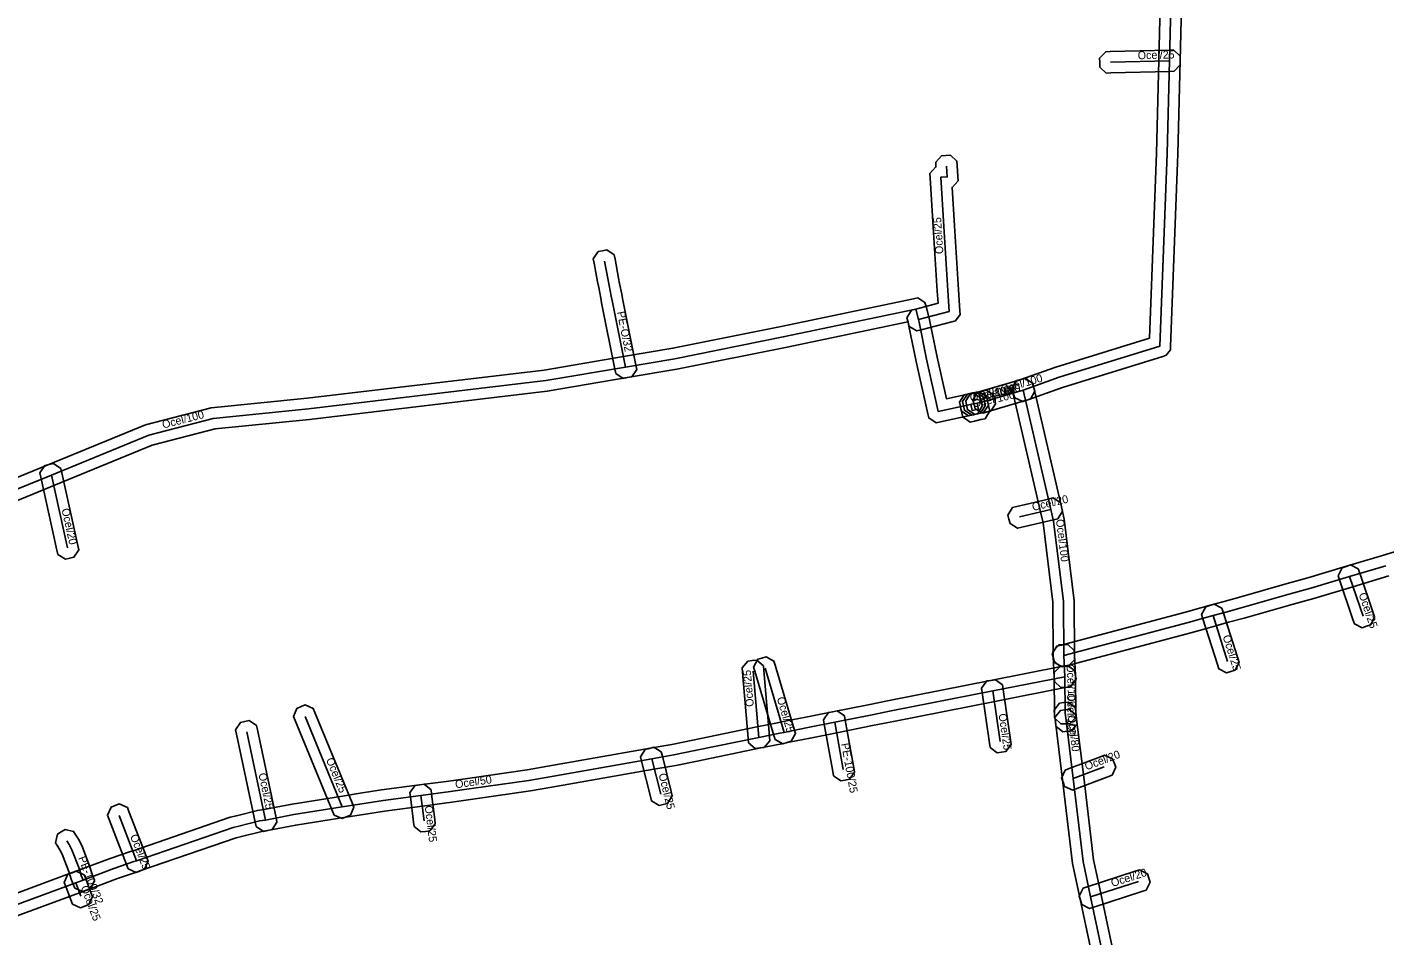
# Model space of a CAD drawing. Extents: x -569373 to -565022, y -1135090 to -1131496.
# Drawn here: x -565551.4 to -565424.2, y -1133791.5 to -1133706.4 of the extents above; entities that cross this region are included whole.
import ezdxf

# ---------------------------------------------------------------- set-up
doc = ezdxf.new("R2010")
doc.units = 0
for name, color, linetype in [('1', 7, 'Continuous'), ('24', 7, 'Continuous'), ('30', 7, 'Continuous')]:
    doc.layers.add(name, color=color, linetype=linetype)

msp = doc.modelspace()

# ---------------------------------------------------------------- linework, layer by layer
at = {"layer": '1'}
for points in [[(-565443.139, -1133700.516), (-565443.35, -1133709.573), (-565443.55, -1133718.271), (-565444.251, -1133736.319), (-565444.263, -1133736.637), (-565444.651, -1133737.142), (-565444.955, -1133737.236), (-565454.374, -1133740.139), (-565457.703, -1133741.331), (-565458.093, -1133741.471), (-565458.841, -1133741.117), (-565458.981, -1133740.727), (-565459.121, -1133740.337), (-565458.767, -1133739.589), (-565458.377, -1133739.449), (-565455.006, -1133738.241), (-565446.222, -1133735.533), (-565445.55, -1133718.209), (-565445.35, -1133709.527), (-565445.141, -1133700.544)], [(-565553.833, -1133749.207), (-565549.479, -1133747.425), (-565540.286, -1133743.659), (-565534.116, -1133742.063), (-565525.119, -1133741.166), (-565502.923, -1133738.52), (-565495.492, -1133737.26), (-565490.872, -1133736.477), (-565480.731, -1133734.44), (-565468.325, -1133731.841), (-565467.933, -1133731.759), (-565467.253, -1133732.181), (-565467.152, -1133732.568), (-565466.9, -1133733.537), (-565466.834, -1133733.813), (-565466.122, -1133737.301), (-565465.251, -1133741.203), (-565463.227, -1133740.766), (-565463.203, -1133740.76), (-565462.801, -1133740.659), (-565462.09, -1133741.085), (-565461.99, -1133741.487), (-565461.889, -1133741.889), (-565462.315, -1133742.6), (-565462.717, -1133742.7), (-565462.773, -1133742.714), (-565465.799, -1133743.367), (-565466.202, -1133743.454), (-565466.896, -1133743.01), (-565466.986, -1133742.608), (-565468.078, -1133737.719), (-565468.786, -1133734.247), (-565468.84, -1133734.023), (-565468.848, -1133733.994), (-565480.329, -1133736.4), (-565490.508, -1133738.443), (-565495.158, -1133739.232), (-565502.637, -1133740.5), (-565524.901, -1133743.154), (-565533.764, -1133744.037), (-565539.654, -1133745.561), (-565548.721, -1133749.275), (-565552.967, -1133751.013)], [(-565423.803, -1133757.8), (-565427.184, -1133758.808), (-565430.831, -1133759.9), (-565432.767, -1133760.447), (-565437.351, -1133761.743), (-565438.803, -1133762.144), (-565439.995, -1133762.474), (-565440.885, -1133762.718), (-565442.34, -1133763.116), (-565453.994, -1133766.207), (-565454.394, -1133766.313), (-565455.111, -1133765.897), (-565455.217, -1133765.496), (-565455.323, -1133765.096), (-565454.907, -1133764.379), (-565454.506, -1133764.273), (-565442.86, -1133761.184), (-565441.413, -1133760.788), (-565440.525, -1133760.546), (-565439.337, -1133760.216), (-565437.889, -1133759.817), (-565433.311, -1133758.523), (-565431.389, -1133757.98), (-565427.756, -1133756.892), (-565424.375, -1133755.884), (-565422.452, -1133755.31)], [(-565553.339, -1133787.878), (-565547.156, -1133785.592), (-565546.477, -1133785.342), (-565543.587, -1133784.268), (-565541.681, -1133783.613), (-565541.441, -1133783.533), (-565532.353, -1133780.4), (-565531.77, -1133780.256), (-565529.789, -1133779.769), (-565529.204, -1133779.675), (-565526.542, -1133779.165), (-565523.985, -1133778.762), (-565522.006, -1133778.452), (-565520.159, -1133778.158), (-565518.174, -1133777.84), (-565514.6, -1133777.369), (-565511.856, -1133777.009), (-565509.881, -1133776.727), (-565504.527, -1133775.962), (-565502.572, -1133775.618), (-565493.003, -1133773.935), (-565490.957, -1133773.578), (-565489.013, -1133773.177), (-565483.019, -1133771.94), (-565481.056, -1133771.549), (-565480.656, -1133771.469), (-565480.375, -1133771.413), (-565478.416, -1133771.019), (-565475.905, -1133770.519), (-565472.565, -1133769.859), (-565470.605, -1133769.469), (-565461.104, -1133767.589), (-565454.343, -1133766.259), (-565453.937, -1133766.179), (-565453.249, -1133766.641), (-565453.169, -1133767.047), (-565453.089, -1133767.453), (-565453.551, -1133768.141), (-565453.957, -1133768.221), (-565460.716, -1133769.551), (-565470.215, -1133771.431), (-565472.175, -1133771.821), (-565475.515, -1133772.481), (-565478.024, -1133772.981), (-565479.983, -1133773.375), (-565480.264, -1133773.431), (-565480.664, -1133773.511), (-565482.621, -1133773.9), (-565488.609, -1133775.135), (-565490.583, -1133775.542), (-565492.657, -1133775.905), (-565502.226, -1133777.588), (-565504.213, -1133777.938), (-565509.599, -1133778.707), (-565511.584, -1133778.991), (-565514.34, -1133779.351), (-565517.886, -1133779.82), (-565519.843, -1133780.132), (-565521.694, -1133780.428), (-565523.675, -1133780.738), (-565526.198, -1133781.135), (-565528.856, -1133781.645), (-565529.391, -1133781.731), (-565531.292, -1133782.198), (-565531.787, -1133782.32), (-565540.799, -1133785.427), (-565541.039, -1133785.507), (-565542.913, -1133786.152), (-565545.783, -1133787.218), (-565546.464, -1133787.468), (-565552.645, -1133789.754)], [(-565448.326, -1133808.76), (-565452.718, -1133788.077), (-565453.428, -1133784.724), (-565454.373, -1133776.89), (-565455.033, -1133771.471), (-565455.083, -1133771.06), (-565454.572, -1133770.407), (-565454.161, -1133770.357), (-565453.75, -1133770.307), (-565453.097, -1133770.818), (-565453.047, -1133771.229), (-565452.387, -1133776.65), (-565451.452, -1133784.396), (-565450.762, -1133787.663), (-565446.374, -1133808.32)]]:
    msp.add_lwpolyline(points, dxfattribs=at)
for points in [[(-565443.909, -1133710.539), (-565444.323, -1133710.55), (-565449.853, -1133710.7), (-565450.267, -1133710.711), (-565450.869, -1133710.141), (-565450.88, -1133709.727), (-565450.891, -1133709.313), (-565450.321, -1133708.711), (-565449.907, -1133708.7), (-565444.377, -1133708.55), (-565443.963, -1133708.539), (-565443.361, -1133709.109), (-565443.35, -1133709.523), (-565443.339, -1133709.937)], [(-565466.237, -1133719.492), (-565466.227, -1133719.492), (-565466.228, -1133719.479), (-565466.252, -1133719.065), (-565465.702, -1133718.446), (-565465.289, -1133718.422), (-565464.875, -1133718.398), (-565464.256, -1133718.948), (-565464.232, -1133719.361), (-565464.172, -1133720.381), (-565464.147, -1133720.797), (-565464.426, -1133721.108), (-565464.704, -1133721.418), (-565464.708, -1133721.418), (-565464.482, -1133725.017), (-565464.102, -1133731.008), (-565463.982, -1133732.969), (-565463.96, -1133733.327), (-565464.382, -1133733.908), (-565464.729, -1133733.998), (-565467.619, -1133734.748), (-565468.02, -1133734.852), (-565468.734, -1133734.432), (-565468.838, -1133734.031), (-565468.942, -1133733.63), (-565468.522, -1133732.916), (-565468.121, -1133732.812), (-565466.028, -1133732.269), (-565466.098, -1133731.132), (-565466.478, -1133725.143), (-565466.768, -1133720.533), (-565466.794, -1133720.116), (-565466.516, -1133719.804)], [(-565496.225, -1133738.848), (-565496.306, -1133738.442), (-565497.547, -1133732.217), (-565497.632, -1133731.791), (-565497.824, -1133730.776), (-565497.92, -1133730.274), (-565498.253, -1133728.516), (-565498.33, -1133728.109), (-565497.863, -1133727.424), (-565497.456, -1133727.347), (-565497.049, -1133727.27), (-565496.364, -1133727.737), (-565496.287, -1133728.144), (-565495.954, -1133729.902), (-565495.86, -1133730.404), (-565495.668, -1133731.409), (-565495.585, -1133731.825), (-565494.344, -1133738.05), (-565494.263, -1133738.456), (-565494.723, -1133739.146), (-565495.129, -1133739.227), (-565495.535, -1133739.308)], [(-565462.38, -1133740.628), (-565461.983, -1133740.511), (-565458.323, -1133739.431), (-565457.926, -1133739.314), (-565457.198, -1133739.71), (-565457.081, -1133740.107), (-565456.964, -1133740.504), (-565457.36, -1133741.232), (-565457.757, -1133741.349), (-565461.417, -1133742.429), (-565461.814, -1133742.546), (-565462.542, -1133742.15), (-565462.659, -1133741.753), (-565462.776, -1133741.356)], [(-565457.159, -1133739.761), (-565457.066, -1133740.164), (-565454.476, -1133751.345), (-565454.214, -1133752.486), (-565453.27, -1133760.127), (-565453.25, -1133765.236), (-565453.248, -1133765.65), (-565453.832, -1133766.238), (-565454.246, -1133766.24), (-565454.66, -1133766.242), (-565455.248, -1133765.658), (-565455.25, -1133765.244), (-565455.27, -1133760.253), (-565456.186, -1133752.834), (-565456.424, -1133751.795), (-565459.014, -1133740.616), (-565459.108, -1133740.212), (-565458.669, -1133739.509), (-565458.266, -1133739.416), (-565457.862, -1133739.322)], [(-565462.771, -1133740.664), (-565462.762, -1133740.669), (-565462.586, -1133740.632), (-565462.181, -1133740.546), (-565461.486, -1133740.997), (-565461.4, -1133741.402), (-565461.334, -1133741.714), (-565461.276, -1133741.965), (-565461.182, -1133742.371), (-565461.404, -1133742.723), (-565461.625, -1133743.075), (-565462.031, -1133743.166), (-565462.611, -1133743.296), (-565463.017, -1133743.387), (-565463.367, -1133743.164), (-565463.717, -1133742.941), (-565463.807, -1133742.535), (-565463.937, -1133741.945), (-565464.026, -1133741.541), (-565463.58, -1133740.842), (-565463.175, -1133740.753)], [(-565463.568, -1133740.835), (-565463.162, -1133740.751), (-565462.871, -1133740.691), (-565462.465, -1133740.607), (-565461.774, -1133741.062), (-565461.69, -1133741.468), (-565461.606, -1133741.874), (-565462.061, -1133742.565), (-565462.467, -1133742.649), (-565462.758, -1133742.709), (-565463.164, -1133742.793), (-565463.855, -1133742.338), (-565463.939, -1133741.932), (-565464.023, -1133741.526)], [(-565463.277, -1133740.775), (-565462.871, -1133740.691), (-565462.58, -1133740.631), (-565462.174, -1133740.547), (-565461.483, -1133741.002), (-565461.399, -1133741.408), (-565461.315, -1133741.814), (-565461.77, -1133742.505), (-565462.176, -1133742.589), (-565462.467, -1133742.649), (-565462.873, -1133742.733), (-565463.564, -1133742.278), (-565463.648, -1133741.872), (-565463.732, -1133741.466)], [(-565462.986, -1133740.715), (-565462.58, -1133740.631), (-565461.902, -1133740.491), (-565461.496, -1133740.407), (-565460.805, -1133740.862), (-565460.721, -1133741.268), (-565460.637, -1133741.674), (-565461.092, -1133742.365), (-565461.498, -1133742.449), (-565462.176, -1133742.589), (-565462.582, -1133742.673), (-565463.273, -1133742.218), (-565463.357, -1133741.812), (-565463.441, -1133741.406)], [(-565548.212, -1133747.73), (-565548.123, -1133748.135), (-565546.623, -1133754.945), (-565546.534, -1133755.349), (-565546.98, -1133756.048), (-565547.385, -1133756.137), (-565547.789, -1133756.226), (-565548.488, -1133755.78), (-565548.577, -1133755.375), (-565550.077, -1133748.565), (-565550.166, -1133748.161), (-565549.72, -1133747.462), (-565549.315, -1133747.373), (-565548.911, -1133747.284)], [(-565454.817, -1133752.448), (-565455.22, -1133752.543), (-565458.18, -1133753.243), (-565458.583, -1133753.338), (-565459.288, -1133752.903), (-565459.383, -1133752.5), (-565459.478, -1133752.097), (-565459.043, -1133751.392), (-565458.64, -1133751.297), (-565455.68, -1133750.597), (-565455.277, -1133750.502), (-565454.572, -1133750.937), (-565454.477, -1133751.34), (-565454.382, -1133751.743)], [(-565426.656, -1133757.137), (-565426.523, -1133757.529), (-565425.263, -1133761.249), (-565425.13, -1133761.641), (-565425.497, -1133762.384), (-565425.889, -1133762.517), (-565426.281, -1133762.65), (-565427.024, -1133762.283), (-565427.157, -1133761.891), (-565428.417, -1133758.171), (-565428.55, -1133757.779), (-565428.183, -1133757.036), (-565427.791, -1133756.903), (-565427.399, -1133756.77)], [(-565439.432, -1133760.813), (-565439.307, -1133761.208), (-565437.947, -1133765.508), (-565437.822, -1133765.903), (-565438.203, -1133766.638), (-565438.598, -1133766.763), (-565438.993, -1133766.888), (-565439.728, -1133766.507), (-565439.853, -1133766.112), (-565441.213, -1133761.812), (-565441.338, -1133761.417), (-565440.957, -1133760.682), (-565440.562, -1133760.557), (-565440.167, -1133760.432)], [(-565453.272, -1133764.776), (-565453.251, -1133765.19), (-565453.151, -1133767.19), (-565453.13, -1133767.604), (-565453.686, -1133768.218), (-565454.1, -1133768.239), (-565454.514, -1133768.26), (-565455.128, -1133767.704), (-565455.149, -1133767.29), (-565455.249, -1133765.29), (-565455.27, -1133764.876), (-565454.714, -1133764.262), (-565454.3, -1133764.241), (-565453.886, -1133764.22)], [(-565483.781, -1133773.418), (-565483.816, -1133773.005), (-565484.346, -1133766.815), (-565484.382, -1133766.402), (-565483.848, -1133765.769), (-565483.435, -1133765.734), (-565483.022, -1133765.698), (-565482.389, -1133766.232), (-565482.354, -1133766.645), (-565481.824, -1133772.835), (-565481.788, -1133773.248), (-565482.322, -1133773.881), (-565482.735, -1133773.916), (-565483.148, -1133773.952)], [(-565481.301, -1133773.131), (-565481.419, -1133772.734), (-565483.199, -1133766.734), (-565483.317, -1133766.337), (-565482.921, -1133765.609), (-565482.524, -1133765.491), (-565482.127, -1133765.373), (-565481.399, -1133765.769), (-565481.281, -1133766.166), (-565479.501, -1133772.166), (-565479.383, -1133772.563), (-565479.779, -1133773.291), (-565480.176, -1133773.409), (-565480.573, -1133773.527)], [(-565453.154, -1133766.817), (-565453.15, -1133767.231), (-565453.12, -1133770.651), (-565453.116, -1133771.065), (-565453.697, -1133771.656), (-565454.111, -1133771.66), (-565454.525, -1133771.664), (-565455.116, -1133771.083), (-565455.12, -1133770.669), (-565455.15, -1133767.249), (-565455.154, -1133766.835), (-565454.573, -1133766.244), (-565454.159, -1133766.24), (-565453.745, -1133766.236)], [(-565459.98, -1133768.016), (-565459.92, -1133768.426), (-565459.23, -1133773.166), (-565459.17, -1133773.576), (-565459.666, -1133774.24), (-565460.076, -1133774.3), (-565460.486, -1133774.36), (-565461.15, -1133773.864), (-565461.21, -1133773.454), (-565461.9, -1133768.714), (-565461.96, -1133768.304), (-565461.464, -1133767.64), (-565461.054, -1133767.58), (-565460.644, -1133767.52)], [(-565522.618, -1133780.203), (-565522.775, -1133779.82), (-565526.255, -1133771.35), (-565526.412, -1133770.967), (-565526.093, -1133770.202), (-565525.71, -1133770.045), (-565525.327, -1133769.888), (-565524.562, -1133770.207), (-565524.405, -1133770.59), (-565520.925, -1133779.06), (-565520.768, -1133779.443), (-565521.087, -1133780.208), (-565521.47, -1133780.365), (-565521.853, -1133780.522)], [(-565453.175, -1133770.133), (-565453.127, -1133770.545), (-565453.047, -1133771.235), (-565452.999, -1133771.646), (-565453.513, -1133772.295), (-565453.925, -1133772.343), (-565454.336, -1133772.391), (-565454.985, -1133771.877), (-565455.033, -1133771.465), (-565455.113, -1133770.775), (-565455.161, -1133770.364), (-565454.647, -1133769.715), (-565454.235, -1133769.667), (-565453.824, -1133769.619)], [(-565529.922, -1133781.273), (-565530.008, -1133780.868), (-565531.758, -1133772.618), (-565531.844, -1133772.212), (-565531.393, -1133771.518), (-565530.988, -1133771.432), (-565530.582, -1133771.346), (-565529.888, -1133771.797), (-565529.802, -1133772.202), (-565528.052, -1133780.452), (-565527.966, -1133780.858), (-565528.417, -1133781.552), (-565528.822, -1133781.638), (-565529.228, -1133781.724)], [(-565475.821, -1133776.525), (-565475.894, -1133776.117), (-565476.694, -1133771.677), (-565476.767, -1133771.269), (-565476.295, -1133770.589), (-565475.887, -1133770.516), (-565475.479, -1133770.443), (-565474.799, -1133770.915), (-565474.726, -1133771.323), (-565473.926, -1133775.763), (-565473.853, -1133776.171), (-565474.325, -1133776.851), (-565474.733, -1133776.924), (-565475.141, -1133776.997)], [(-565491.959, -1133774.278), (-565491.859, -1133774.68), (-565491.039, -1133777.99), (-565490.94, -1133778.392), (-565491.368, -1133779.101), (-565491.77, -1133779.201), (-565492.172, -1133779.3), (-565492.881, -1133778.872), (-565492.981, -1133778.47), (-565493.801, -1133775.16), (-565493.9, -1133774.758), (-565493.472, -1133774.049), (-565493.07, -1133773.949), (-565492.668, -1133773.85)], [(-565454.121, -1133775.981), (-565453.734, -1133775.835), (-565450.824, -1133774.735), (-565450.436, -1133774.588), (-565449.681, -1133774.929), (-565449.535, -1133775.316), (-565449.388, -1133775.704), (-565449.729, -1133776.459), (-565450.116, -1133776.605), (-565453.026, -1133777.705), (-565453.414, -1133777.852), (-565454.169, -1133777.511), (-565454.315, -1133777.124), (-565454.462, -1133776.736)], [(-565513.528, -1133777.828), (-565513.477, -1133778.239), (-565513.187, -1133780.609), (-565513.137, -1133781.02), (-565513.648, -1133781.672), (-565514.059, -1133781.723), (-565514.47, -1133781.773), (-565515.122, -1133781.262), (-565515.173, -1133780.851), (-565515.463, -1133778.481), (-565515.513, -1133778.07), (-565515.002, -1133777.418), (-565514.591, -1133777.367), (-565514.18, -1133777.317)], [(-565541.903, -1133785.227), (-565542.053, -1133784.841), (-565543.693, -1133780.601), (-565543.842, -1133780.215), (-565543.507, -1133779.457), (-565543.121, -1133779.307), (-565542.735, -1133779.158), (-565541.977, -1133779.493), (-565541.827, -1133779.879), (-565540.187, -1133784.119), (-565540.038, -1133784.505), (-565540.373, -1133785.263), (-565540.759, -1133785.413), (-565541.145, -1133785.562)], [(-565546.902, -1133787.039), (-565547.057, -1133786.655), (-565547.246, -1133786.187), (-565547.419, -1133785.589), (-565548.086, -1133783.865), (-565548.293, -1133783.451), (-565548.487, -1133783.142), (-565548.707, -1133782.792), (-565548.523, -1133781.984), (-565548.172, -1133781.763), (-565547.822, -1133781.543), (-565547.014, -1133781.727), (-565546.793, -1133782.078), (-565546.547, -1133782.469), (-565546.254, -1133783.055), (-565545.521, -1133784.951), (-565545.354, -1133785.533), (-565545.203, -1133785.905), (-565545.048, -1133786.289), (-565545.371, -1133787.052), (-565545.755, -1133787.207), (-565546.139, -1133787.362)], [(-565446.537, -1133787.233), (-565446.931, -1133787.361), (-565451.431, -1133788.821), (-565451.825, -1133788.949), (-565452.563, -1133788.573), (-565452.691, -1133788.179), (-565452.819, -1133787.785), (-565452.443, -1133787.047), (-565452.049, -1133786.919), (-565447.549, -1133785.459), (-565447.155, -1133785.331), (-565446.417, -1133785.707), (-565446.289, -1133786.101), (-565446.161, -1133786.495)], [(-565546.023, -1133785.787), (-565545.876, -1133786.174), (-565545.396, -1133787.434), (-565545.249, -1133787.821), (-565545.587, -1133788.577), (-565545.974, -1133788.724), (-565546.361, -1133788.871), (-565547.117, -1133788.533), (-565547.264, -1133788.146), (-565547.744, -1133786.886), (-565547.891, -1133786.499), (-565547.553, -1133785.743), (-565547.166, -1133785.596), (-565546.779, -1133785.449)]]:
    msp.add_lwpolyline(points, close=True, dxfattribs=at)
at = {"layer": '24'}
for points in [[(-565458.04, -1133740.39), (-565454.69, -1133739.19), (-565445.25, -1133736.28), (-565444.55, -1133718.24), (-565444.35, -1133709.55), (-565444.14, -1133700.53), (-565444.51, -1133693.36), (-565445.13, -1133681.36), (-565446.69, -1133669.3), (-565450.02, -1133658.48), (-565450.93, -1133655.51)], [(-565444.35, -1133709.55), (-565449.88, -1133709.7)], [(-565467.87, -1133733.78), (-565464.98, -1133733.03), (-565465.1, -1133731.07), (-565465.48, -1133725.08), (-565465.77, -1133720.47), (-565465.17, -1133720.44), (-565465.23, -1133719.42)], [(-565495.325, -1133738.246), (-565496.566, -1133732.021), (-565496.65, -1133731.6), (-565496.842, -1133730.59), (-565496.937, -1133730.088), (-565497.27, -1133728.33)], [(-565553.4, -1133750.11), (-565549.1, -1133748.35), (-565539.97, -1133744.61), (-565533.94, -1133743.05), (-565525.01, -1133742.16), (-565502.78, -1133739.51), (-565495.325, -1133738.246), (-565490.69, -1133737.46), (-565480.53, -1133735.42), (-565468.12, -1133732.82), (-565467.87, -1133733.78), (-565467.81, -1133734.03), (-565467.1, -1133737.51), (-565466.01, -1133742.39), (-565463, -1133741.74), (-565462.96, -1133741.73)], [(-565461.7, -1133741.47), (-565458.04, -1133740.39)], [(-565458.04, -1133740.39), (-565455.45, -1133751.57), (-565455.2, -1133752.66), (-565454.27, -1133760.19), (-565454.25, -1133765.24)], [(-565462.96, -1133741.73), (-565462.83, -1133742.32), (-565462.25, -1133742.19), (-565462.31, -1133741.93), (-565462.378, -1133741.61)], [(-565462.96, -1133741.73), (-565462.669, -1133741.67)], [(-565462.669, -1133741.67), (-565462.378, -1133741.61)], [(-565462.378, -1133741.61), (-565461.7, -1133741.47)], [(-565549.1, -1133748.35), (-565547.6, -1133755.16)], [(-565455.45, -1133751.57), (-565458.41, -1133752.27)], [(-565424.089, -1133756.842), (-565427.47, -1133757.85), (-565431.11, -1133758.94), (-565433.039, -1133759.485), (-565437.62, -1133760.78), (-565439.07, -1133761.18), (-565440.26, -1133761.51), (-565441.149, -1133761.753), (-565442.6, -1133762.15), (-565454.25, -1133765.24)], [(-565427.47, -1133757.85), (-565426.21, -1133761.57)], [(-565440.26, -1133761.51), (-565438.9, -1133765.81)], [(-565454.25, -1133765.24), (-565454.15, -1133767.24)], [(-565454.15, -1133767.24), (-565460.91, -1133768.57), (-565470.41, -1133770.45), (-565472.37, -1133770.84), (-565475.71, -1133771.5), (-565478.22, -1133772), (-565480.179, -1133772.394), (-565480.46, -1133772.45), (-565480.86, -1133772.53), (-565482.82, -1133772.92), (-565488.811, -1133774.156), (-565490.77, -1133774.56), (-565492.83, -1133774.92), (-565502.399, -1133776.603), (-565504.37, -1133776.95), (-565509.74, -1133777.717), (-565511.72, -1133778), (-565514.47, -1133778.36), (-565518.03, -1133778.83), (-565520.001, -1133779.145), (-565521.85, -1133779.44), (-565523.83, -1133779.75), (-565526.37, -1133780.15), (-565529.03, -1133780.66), (-565529.59, -1133780.75), (-565531.531, -1133781.227), (-565532.07, -1133781.36), (-565541.12, -1133784.48), (-565541.36, -1133784.56), (-565543.25, -1133785.21), (-565546.13, -1133786.28), (-565546.81, -1133786.53), (-565552.992, -1133788.816)], [(-565482.82, -1133772.92), (-565483.35, -1133766.73)], [(-565480.46, -1133772.45), (-565482.24, -1133766.45)], [(-565454.15, -1133767.24), (-565454.12, -1133770.66)], [(-565460.91, -1133768.57), (-565460.22, -1133773.31)], [(-565521.85, -1133779.44), (-565525.33, -1133770.97)], [(-565454.12, -1133770.66), (-565454.04, -1133771.35)], [(-565454.04, -1133771.35), (-565453.38, -1133776.77), (-565452.44, -1133784.56), (-565451.74, -1133787.87), (-565447.35, -1133808.54), (-565445.6, -1133815.89), (-565441.96, -1133831.12), (-565440.86, -1133835.19), (-565437.21, -1133839.75)], [(-565529.03, -1133780.66), (-565530.78, -1133772.41)], [(-565474.91, -1133775.94), (-565475.71, -1133771.5)], [(-565492.83, -1133774.92), (-565492.01, -1133778.23)], [(-565453.38, -1133776.77), (-565450.47, -1133775.67)], [(-565514.47, -1133778.36), (-565514.18, -1133780.73)], [(-565541.12, -1133784.48), (-565542.76, -1133780.24)], [(-565546.13, -1133786.28), (-565546.3, -1133785.86), (-565546.47, -1133785.27), (-565547.17, -1133783.46), (-565547.42, -1133782.96), (-565547.64, -1133782.61)], [(-565546.81, -1133786.53), (-565546.33, -1133787.79)], [(-565447.24, -1133786.41), (-565451.74, -1133787.87)]]:
    msp.add_lwpolyline(points, dxfattribs=at)

# ---------------------------------------------------------------- texts
at = {"layer": '30'}
for s, rotation, p in [('Ocel/25', 1.55375, (-565447.315, -1133709.425)), ('Ocel/25', 93.62993, (-565465.531, -1133727.63)), ('PE-O/32', 281.27453, (-565496.113, -1133733.091)), ('Ocel/100', 16.44038, (-565460.022, -1133740.716)), ('Ocel/100', 11.6503, (-565462.966, -1133741.49)), ('Ocel/100', 12.63336, (-565462.696, -1133742.045)), ('Ocel/100', 11.6503, (-565462.675, -1133741.43)), ('Ocel/100', 11.66701, (-565462.19, -1133741.33)), ('Ocel/100', 14.50477, (-565538.621, -1133744.009)), ('Ocel/20', 13.30524, (-565457.13, -1133751.72)), ('Ocel/20', 282.42186, (-565548.15, -1133751.555)), ('Ocel/100', 277.04072, (-565454.991, -1133752.531)), ('Ocel/25', 288.71174, (-565426.64, -1133759.51)), ('Ocel/25', 287.55107, (-565439.38, -1133763.46)), ('Ocel/100', 272.86241, (-565453.998, -1133766.09)), ('Ocel/25', 94.89384, (-565483.285, -1133770.025)), ('Ocel/100', 270.50258, (-565453.935, -1133768.8)), ('Ocel/25', 286.52387, (-565481.15, -1133769.25)), ('Ocel/25', 278.28235, (-565460.365, -1133770.74)), ('Ocel/80', 276.61346, (-565453.874, -1133770.855)), ('PE-100/25', 280.21397, (-565475.11, -1133773.52)), ('Ocel/25', 292.33589, (-565523.39, -1133775.005)), ('Ocel/20', 20.70694, (-565452.125, -1133776.02)), ('Ocel/25', 281.97613, (-565529.705, -1133776.335)), ('Ocel/50', 8.13415, (-565511.219, -1133777.7)), ('Ocel/25', 283.91399, (-565492.22, -1133776.375)), ('Ocel/25', 276.9762, (-565514.125, -1133779.345)), ('Ocel/25', 291.14609, (-565541.74, -1133782.16)), ('PE-100/32', 291.1435, (-565546.603, -1133784.209)), ('Ocel/20', 17.97537, (-565449.69, -1133786.94)), ('Ocel/25', 290.85446, (-565546.37, -1133786.96))]:
    msp.add_text(s, height=0.75, rotation=rotation, dxfattribs=at).set_placement(p)

doc.saveas('drawing.dxf')
